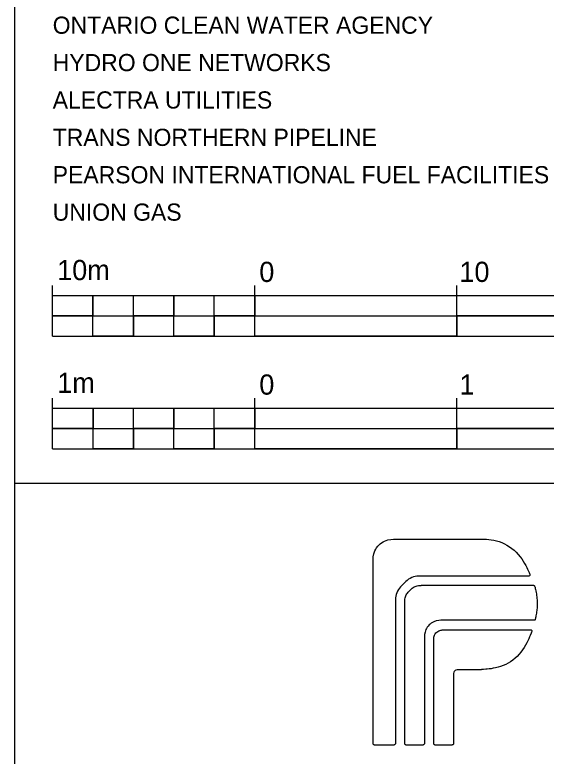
# Model space of a CAD drawing. Extents: x 613360 to 613780, y 4825621 to 4825911.
# Drawn here: x 613710.78 to 613737.07, y 4825658.01 to 4825694.7 of the extents above; entities that cross this region are included whole.
import ezdxf

# ---------------------------------------------------------------- set-up
doc = ezdxf.new("R2010")
doc.units = 0
for name, color, linetype in [('G-ANNO-BAR', 7, 'Continuous'), ('G-ANNO-TEXT', 7, 'Continuous'), ('G-TTLB-LOGO', 7, 'Continuous'), ('G-TTLB-OTLN', 7, 'Continuous')]:
    doc.layers.add(name, color=color, linetype=linetype)

msp = doc.modelspace()

# ---------------------------------------------------------------- linework, layer by layer
at = {"layer": 'G-ANNO-BAR'}
for p, q in [((613712.645, 4825678.805), (613712.645, 4825681.305)), ((613722.645, 4825678.805), (613722.645, 4825681.305)), ((613732.645, 4825678.805), (613732.645, 4825681.305)), ((613712.645, 4825680.805), (613752.645, 4825680.805)), ((613714.645, 4825678.805), (613714.645, 4825680.805)), ((613716.645, 4825678.805), (613716.645, 4825680.805)), ((613718.645, 4825678.805), (613718.645, 4825680.805)), ((613720.645, 4825678.805), (613720.645, 4825680.805)), ((613712.645, 4825679.805), (613752.645, 4825679.805)), ((613712.645, 4825678.805), (613752.645, 4825678.805)), ((613712.646, 4825673.229), (613712.646, 4825675.729)), ((613722.646, 4825673.229), (613722.646, 4825675.729)), ((613732.646, 4825673.229), (613732.646, 4825675.729)), ((613712.646, 4825675.229), (613752.646, 4825675.229)), ((613714.646, 4825673.229), (613714.646, 4825675.229)), ((613716.646, 4825673.229), (613716.646, 4825675.229)), ((613718.646, 4825673.229), (613718.646, 4825675.229)), ((613720.646, 4825673.229), (613720.646, 4825675.229)), ((613712.646, 4825674.229), (613752.646, 4825674.229)), ((613712.646, 4825673.229), (613752.646, 4825673.229))]:
    msp.add_line(p, q, dxfattribs=at)
for points in [[(613712.645, 4825680.805), (613714.645, 4825680.805), (613714.645, 4825679.805), (613712.645, 4825679.805)], [(613716.645, 4825680.805), (613718.645, 4825680.805), (613718.645, 4825679.805), (613716.645, 4825679.805)], [(613720.645, 4825680.805), (613722.645, 4825680.805), (613722.645, 4825679.805), (613720.645, 4825679.805)], [(613732.645, 4825680.805), (613742.645, 4825680.805), (613742.645, 4825679.805), (613732.645, 4825679.805)], [(613714.645, 4825679.805), (613716.645, 4825679.805), (613716.645, 4825678.805), (613714.645, 4825678.805)], [(613718.645, 4825679.805), (613720.645, 4825679.805), (613720.645, 4825678.805), (613718.645, 4825678.805)], [(613722.645, 4825679.805), (613732.645, 4825679.805), (613732.645, 4825678.805), (613722.645, 4825678.805)], [(613712.646, 4825675.229), (613714.646, 4825675.229), (613714.646, 4825674.229), (613712.646, 4825674.229)], [(613716.646, 4825675.229), (613718.646, 4825675.229), (613718.646, 4825674.229), (613716.646, 4825674.229)], [(613720.646, 4825675.229), (613722.646, 4825675.229), (613722.646, 4825674.229), (613720.646, 4825674.229)], [(613732.646, 4825675.229), (613742.646, 4825675.229), (613742.646, 4825674.229), (613732.646, 4825674.229)], [(613714.646, 4825674.229), (613716.646, 4825674.229), (613716.646, 4825673.229), (613714.646, 4825673.229)], [(613718.646, 4825674.229), (613720.646, 4825674.229), (613720.646, 4825673.229), (613718.646, 4825673.229)], [(613722.646, 4825674.229), (613732.646, 4825674.229), (613732.646, 4825673.229), (613722.646, 4825673.229)]]:
    msp.add_lwpolyline(points, close=True, dxfattribs=at)
at = {"layer": 'G-TTLB-LOGO'}
for points in [[(613736.212, 4825666.929), (613736.237, 4825666.929), (613736.269, 4825666.956), (613736.269, 4825666.991), (613736.268, 4825667.006), (613736.262, 4825667.023), (613736.261, 4825667.026), (613735.778, 4825668.05), (613734.747, 4825668.752), (613733.665, 4825668.752), (613733.665, 4825668.752), (613729.727, 4825668.752), (613729.727, 4825668.752), (613729.053, 4825668.752), (613728.504, 4825668.203), (613728.504, 4825667.529), (613728.504, 4825667.529), (613728.504, 4825658.65), (613728.504, 4825658.65), (613728.504, 4825658.604), (613728.542, 4825658.567), (613728.588, 4825658.567), (613728.588, 4825658.567), (613729.524, 4825658.567), (613729.524, 4825658.567), (613729.57, 4825658.567), (613729.607, 4825658.604), (613729.607, 4825658.65), (613729.607, 4825658.65), (613729.609, 4825665.583), (613729.609, 4825665.583), (613729.605, 4825665.938), (613729.741, 4825666.276), (613729.992, 4825666.53), (613730.246, 4825666.787), (613730.585, 4825666.929), (613730.946, 4825666.929), (613730.946, 4825666.929), (613736.212, 4825666.929), (613736.212, 4825666.929)], [(613736.212, 4825666.929), (613736.237, 4825666.929), (613736.269, 4825666.956), (613736.269, 4825666.991), (613736.268, 4825667.006), (613736.262, 4825667.023), (613736.261, 4825667.026), (613735.778, 4825668.05), (613734.747, 4825668.752), (613733.665, 4825668.752), (613733.665, 4825668.752), (613729.727, 4825668.752), (613729.727, 4825668.752), (613729.053, 4825668.752), (613728.504, 4825668.203), (613728.504, 4825667.529), (613728.504, 4825667.529), (613728.504, 4825658.65), (613728.504, 4825658.65), (613728.504, 4825658.604), (613728.542, 4825658.567), (613728.588, 4825658.567), (613728.588, 4825658.567), (613729.524, 4825658.567), (613729.524, 4825658.567), (613729.57, 4825658.567), (613729.607, 4825658.604), (613729.607, 4825658.65), (613729.607, 4825658.65), (613729.609, 4825665.583), (613729.609, 4825665.583), (613729.605, 4825665.938), (613729.741, 4825666.276), (613729.992, 4825666.53), (613730.246, 4825666.787), (613730.585, 4825666.929), (613730.946, 4825666.929), (613730.946, 4825666.929), (613736.212, 4825666.929), (613736.212, 4825666.929)], [(613736.487, 4825666.446), (613736.475, 4825666.46), (613736.459, 4825666.469), (613736.439, 4825666.469), (613736.438, 4825666.469), (613730.915, 4825666.469), (613730.915, 4825666.469), (613730.688, 4825666.461), (613730.477, 4825666.37), (613730.318, 4825666.209), (613730.162, 4825666.051), (613730.075, 4825665.846), (613730.068, 4825665.626), (613730.068, 4825665.626), (613730.068, 4825658.65), (613730.068, 4825658.65), (613730.068, 4825658.604), (613730.106, 4825658.567), (613730.152, 4825658.567), (613730.152, 4825658.567), (613730.96, 4825658.567), (613730.96, 4825658.567), (613731.006, 4825658.567), (613731.043, 4825658.604), (613731.043, 4825658.65), (613731.043, 4825658.65), (613731.043, 4825663.75), (613731.043, 4825663.75), (613731.043, 4825664.296), (613731.487, 4825664.74), (613732.033, 4825664.74), (613732.033, 4825664.74), (613736.471, 4825664.74), (613736.471, 4825664.74), (613736.498, 4825664.741), (613736.523, 4825664.761), (613736.529, 4825664.786), (613736.53, 4825664.788), (613736.53, 4825664.788), (613736.53, 4825664.79), (613736.577, 4825665.02), (613736.619, 4825665.283), (613736.619, 4825665.52), (613736.619, 4825665.821), (613736.58, 4825666.118), (613736.506, 4825666.405), (613736.5, 4825666.431), (613736.493, 4825666.44), (613736.487, 4825666.446)], [(613736.487, 4825666.446), (613736.475, 4825666.46), (613736.459, 4825666.469), (613736.439, 4825666.469), (613736.438, 4825666.469), (613730.915, 4825666.469), (613730.915, 4825666.469), (613730.688, 4825666.461), (613730.477, 4825666.37), (613730.318, 4825666.209), (613730.162, 4825666.051), (613730.075, 4825665.846), (613730.068, 4825665.626), (613730.068, 4825665.626), (613730.068, 4825658.65), (613730.068, 4825658.65), (613730.068, 4825658.604), (613730.106, 4825658.567), (613730.152, 4825658.567), (613730.152, 4825658.567), (613730.96, 4825658.567), (613730.96, 4825658.567), (613731.006, 4825658.567), (613731.043, 4825658.604), (613731.043, 4825658.65), (613731.043, 4825658.65), (613731.043, 4825663.75), (613731.043, 4825663.75), (613731.043, 4825664.296), (613731.487, 4825664.74), (613732.033, 4825664.74), (613732.033, 4825664.74), (613736.471, 4825664.74), (613736.471, 4825664.74), (613736.498, 4825664.741), (613736.523, 4825664.761), (613736.529, 4825664.786), (613736.53, 4825664.788), (613736.53, 4825664.788), (613736.53, 4825664.79), (613736.577, 4825665.02), (613736.619, 4825665.283), (613736.619, 4825665.52), (613736.619, 4825665.821), (613736.58, 4825666.118), (613736.506, 4825666.405), (613736.5, 4825666.431), (613736.493, 4825666.44), (613736.487, 4825666.446)], [(613736.288, 4825664.271), (613736.288, 4825664.271), (613732.028, 4825664.271), (613732.006, 4825664.271), (613731.983, 4825664.271), (613731.937, 4825664.267), (613731.921, 4825664.263), (613731.694, 4825664.215), (613731.521, 4825664.017), (613731.508, 4825663.779), (613731.508, 4825663.779), (613731.508, 4825658.65), (613731.508, 4825658.65), (613731.508, 4825658.604), (613731.545, 4825658.567), (613731.592, 4825658.567), (613731.592, 4825658.567), (613732.399, 4825658.567), (613732.399, 4825658.567), (613732.445, 4825658.567), (613732.483, 4825658.604), (613732.483, 4825658.65), (613732.483, 4825658.65), (613732.483, 4825662.035), (613732.483, 4825662.035), (613732.483, 4825662.177), (613732.597, 4825662.291), (613732.739, 4825662.291), (613732.739, 4825662.291), (613733.732, 4825662.291), (613733.732, 4825662.291), (613733.732, 4825662.291), (613733.871, 4825662.295), (613733.907, 4825662.299), (613734.96, 4825662.394), (613735.901, 4825663.105), (613736.347, 4825664.166), (613736.356, 4825664.186), (613736.357, 4825664.217), (613736.348, 4825664.236), (613736.335, 4825664.261), (613736.314, 4825664.271), (613736.288, 4825664.271)], [(613736.288, 4825664.271), (613736.288, 4825664.271), (613732.028, 4825664.271), (613732.006, 4825664.271), (613731.983, 4825664.271), (613731.937, 4825664.267), (613731.921, 4825664.263), (613731.694, 4825664.215), (613731.521, 4825664.017), (613731.508, 4825663.779), (613731.508, 4825663.779), (613731.508, 4825658.65), (613731.508, 4825658.65), (613731.508, 4825658.604), (613731.545, 4825658.567), (613731.592, 4825658.567), (613731.592, 4825658.567), (613732.399, 4825658.567), (613732.399, 4825658.567), (613732.445, 4825658.567), (613732.483, 4825658.604), (613732.483, 4825658.65), (613732.483, 4825658.65), (613732.483, 4825662.035), (613732.483, 4825662.035), (613732.483, 4825662.177), (613732.597, 4825662.291), (613732.739, 4825662.291), (613732.739, 4825662.291), (613733.732, 4825662.291), (613733.732, 4825662.291), (613733.732, 4825662.291), (613733.871, 4825662.295), (613733.907, 4825662.299), (613734.96, 4825662.394), (613735.901, 4825663.105), (613736.347, 4825664.166), (613736.356, 4825664.186), (613736.357, 4825664.217), (613736.348, 4825664.236), (613736.335, 4825664.261), (613736.314, 4825664.271), (613736.288, 4825664.271)]]:
    msp.add_open_spline(points, degree=3, dxfattribs=at)
at = {"layer": 'G-TTLB-OTLN'}
for p, q in [((613710.777, 4825623.508), (613710.777, 4825815.929)), ((613774.178, 4825671.507), (613710.777, 4825671.507))]:
    msp.add_line(p, q, dxfattribs=at)

# ---------------------------------------------------------------- texts
at = {"layer": 'G-ANNO-BAR'}
msp.add_text('10m', height=1, dxfattribs=at).set_placement((613712.873, 4825681.569))
for s, p in [('0', (613722.874, 4825681.478)), ('10', (613732.777, 4825681.48)), ('1m', (613712.876, 4825675.992)), ('0', (613722.874, 4825675.903)), ('1', (613732.778, 4825675.902))]:
    msp.add_text(s, height=1, rotation=360, dxfattribs=at).set_placement(p)
at = {"layer": 'G-ANNO-TEXT'}
for s, p in [('ONTARIO CLEAN WATER AGENCY', (613712.651, 4825693.76)), ('HYDRO ONE NETWORKS', (613712.651, 4825691.91)), ('ALECTRA UTILITIES', (613712.651, 4825690.06)), ('TRANS NORTHERN PIPELINE', (613712.651, 4825688.21)), ('PEARSON INTERNATIONAL FUEL FACILITIES CORP.', (613712.651, 4825686.36)), ('UNION GAS', (613712.651, 4825684.51))]:
    msp.add_text(s, height=0.85, dxfattribs=at).set_placement(p)

doc.saveas('drawing.dxf')
